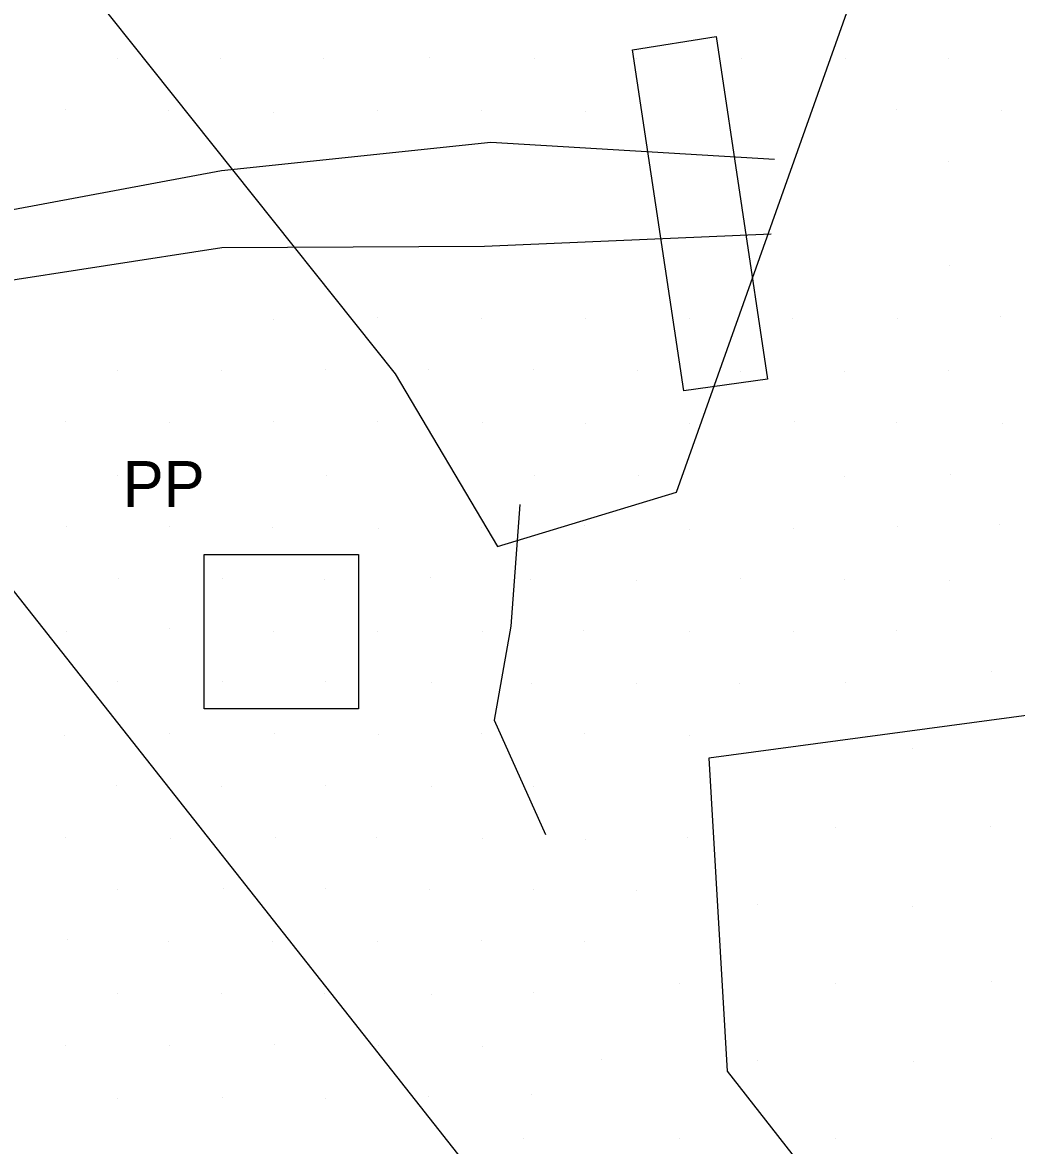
# Model space of a CAD drawing. Extents: x 1602514 to 1609837, y 863887 to 871157.
# Drawn here: x 1605469.8 to 1605605.1, y 866659.7 to 866812.6 of the extents above; entities that cross this region are included whole.
import ezdxf

# ---------------------------------------------------------------- set-up
doc = ezdxf.new("R2010")
doc.units = 0
for name, color, linetype in [('Survey-Flow line', 7, 'Continuous'), ('Survey-Ridge Lines', 7, 'Continuous'), ('Survey-Signs', 7, 'Continuous'), ('Survey-Spot dirt', 7, 'Continuous'), ('Survey-Vegetation trees', 7, 'Continuous'), ('Utility-Pole', 7, 'Continuous')]:
    doc.layers.add(name, color=color, linetype=linetype)

msp = doc.modelspace()

# ---------------------------------------------------------------- linework, layer by layer
at = {"layer": 'Survey-Flow line'}
msp.add_lwpolyline([(1605537.51, 866746.95), (1605536.31, 866730.41), (1605534.05, 866717.59), (1605541.03, 866702.04)], dxfattribs=at)
msp.add_lwpolyline([(1605537.51, 866746.95), (1605536.31, 866730.41), (1605534.05, 866717.59), (1605541.03, 866702.04)], dxfattribs=at)
at = {"layer": 'Survey-Ridge Lines'}
for points in [[(1605271.01, 866733.55), (1605271.13, 866733.84), (1605289.06, 866764.85), (1605290.46, 866799.29), (1605315.08, 866805.27), (1605342.58, 866794.72), (1605372.7, 866790.88), (1605403.41, 866786.28), (1605432.05, 866784.47), (1605463.64, 866786.21), (1605496.91, 866792.44), (1605533.57, 866796.29), (1605572.16, 866793.97)], [(1605271.13, 866733.84), (1605289.06, 866764.85), (1605290.46, 866799.29), (1605315.08, 866805.27), (1605342.58, 866794.72), (1605372.7, 866790.88), (1605403.41, 866786.28), (1605432.05, 866784.47), (1605463.64, 866786.21), (1605496.91, 866792.44), (1605533.57, 866796.29), (1605572.16, 866793.97)], [(1605315.46, 866789.1), (1605342.69, 866785.48), (1605372.69, 866782.64), (1605403.34, 866780.84), (1605431.74, 866777.29), (1605465.29, 866777.04), (1605496.99, 866781.93), (1605532.71, 866782.11), (1605571.74, 866783.81)], [(1605315.46, 866789.1), (1605342.69, 866785.48), (1605372.69, 866782.64), (1605403.34, 866780.84), (1605431.74, 866777.29), (1605465.29, 866777.04), (1605496.99, 866781.93), (1605532.71, 866782.11), (1605571.74, 866783.81)]]:
    msp.add_lwpolyline(points, dxfattribs=at)
at = {"layer": 'Survey-Signs'}
msp.add_lwpolyline([(1605564.25, 866810.68), (1605571.22, 866764.02), (1605559.84, 866762.46), (1605552.88, 866808.83)], close=True, dxfattribs=at)
msp.add_lwpolyline([(1605564.25, 866810.68), (1605571.22, 866764.02), (1605559.84, 866762.46), (1605552.88, 866808.83)], close=True, dxfattribs=at)
at = {"layer": 'Survey-Spot dirt'}
for p, q in [((1605482.8, 866807.68), (1605482.8, 866807.68)), ((1605482.8, 866807.68), (1605482.8, 866807.68)), ((1605496.84, 866807.66), (1605496.84, 866807.66)), ((1605496.84, 866807.66), (1605496.84, 866807.66)), ((1605510.83, 866807.65), (1605510.83, 866807.65)), ((1605510.83, 866807.65), (1605510.83, 866807.65)), ((1605525.29, 866807.83), (1605525.29, 866807.83)), ((1605525.29, 866807.83), (1605525.29, 866807.83)), ((1605539.51, 866807.62), (1605539.51, 866807.62)), ((1605539.51, 866807.62), (1605539.51, 866807.62)), ((1605553.41, 866807.7), (1605553.41, 866807.7)), ((1605553.41, 866807.7), (1605553.41, 866807.7)), ((1605567.74, 866807.66), (1605567.74, 866807.66)), ((1605567.74, 866807.66), (1605567.74, 866807.66)), ((1605581.8, 866807.72), (1605581.8, 866807.72)), ((1605581.8, 866807.72), (1605581.8, 866807.72)), ((1605595.92, 866807.68), (1605595.92, 866807.68)), ((1605595.92, 866807.68), (1605595.92, 866807.68)), ((1605475.72, 866800.69), (1605475.72, 866800.69)), ((1605475.72, 866800.69), (1605475.72, 866800.69)), ((1605489.77, 866800.58), (1605489.77, 866800.58)), ((1605489.77, 866800.58), (1605489.77, 866800.58)), ((1605518.16, 866800.57), (1605518.16, 866800.57)), ((1605518.16, 866800.57), (1605518.16, 866800.57)), ((1605532.26, 866800.62), (1605532.26, 866800.62)), ((1605532.26, 866800.62), (1605532.26, 866800.62)), ((1605546.53, 866800.5), (1605546.53, 866800.5)), ((1605546.53, 866800.5), (1605546.53, 866800.5)), ((1605588.72, 866800.72), (1605588.72, 866800.72)), ((1605588.72, 866800.72), (1605588.72, 866800.72)), ((1605603.04, 866800.62), (1605603.04, 866800.62)), ((1605603.04, 866800.62), (1605603.04, 866800.62)), ((1605504.02, 866800.35), (1605504.02, 866800.35)), ((1605504.02, 866800.35), (1605504.02, 866800.35)), ((1605595.81, 866793.66), (1605595.81, 866793.66)), ((1605595.81, 866793.66), (1605595.81, 866793.66)), ((1605595.99, 866779.44), (1605595.99, 866779.44)), ((1605595.99, 866779.44), (1605595.99, 866779.44)), ((1605504.06, 866772.2), (1605504.06, 866772.2)), ((1605504.06, 866772.2), (1605504.06, 866772.2)), ((1605518.18, 866772.41), (1605518.18, 866772.41)), ((1605518.18, 866772.41), (1605518.18, 866772.41)), ((1605532.32, 866772.28), (1605532.32, 866772.28)), ((1605532.32, 866772.28), (1605532.32, 866772.28)), ((1605546.44, 866772.24), (1605546.44, 866772.24)), ((1605546.44, 866772.24), (1605546.44, 866772.24)), ((1605560.68, 866772.32), (1605560.68, 866772.32)), ((1605560.68, 866772.32), (1605560.68, 866772.32)), ((1605574.59, 866772.26), (1605574.59, 866772.26)), ((1605574.59, 866772.26), (1605574.59, 866772.26)), ((1605588.95, 866772.33), (1605588.95, 866772.33)), ((1605588.95, 866772.33), (1605588.95, 866772.33)), ((1605602.98, 866772.55), (1605602.98, 866772.55)), ((1605602.98, 866772.55), (1605602.98, 866772.55)), ((1605482.83, 866765.27), (1605482.83, 866765.27)), ((1605482.83, 866765.27), (1605482.83, 866765.27)), ((1605511.04, 866765.3), (1605511.04, 866765.3)), ((1605511.04, 866765.3), (1605511.04, 866765.3)), ((1605525.12, 866765.34), (1605525.12, 866765.34)), ((1605525.12, 866765.34), (1605525.12, 866765.34)), ((1605539.32, 866765.3), (1605539.32, 866765.3)), ((1605539.32, 866765.3), (1605539.32, 866765.3)), ((1605496.96, 866765.2), (1605496.96, 866765.2)), ((1605496.96, 866765.2), (1605496.96, 866765.2)), ((1605553.6, 866765.22), (1605553.6, 866765.22)), ((1605553.6, 866765.22), (1605553.6, 866765.22)), ((1605567.6, 866765.08), (1605567.6, 866765.08)), ((1605567.6, 866765.08), (1605567.6, 866765.08)), ((1605581.7, 866765.09), (1605581.7, 866765.09)), ((1605581.7, 866765.09), (1605581.7, 866765.09)), ((1605595.9, 866765.16), (1605595.9, 866765.16)), ((1605595.9, 866765.16), (1605595.9, 866765.16)), ((1605475.7, 866758.31), (1605475.7, 866758.31)), ((1605475.7, 866758.31), (1605475.7, 866758.31)), ((1605489.85, 866758.13), (1605489.85, 866758.13)), ((1605489.85, 866758.13), (1605489.85, 866758.13)), ((1605503.99, 866758.25), (1605503.99, 866758.25)), ((1605503.99, 866758.25), (1605503.99, 866758.25)), ((1605518.11, 866758.24), (1605518.11, 866758.24)), ((1605518.11, 866758.24), (1605518.11, 866758.24)), ((1605532.4, 866758.08), (1605532.4, 866758.08)), ((1605532.4, 866758.08), (1605532.4, 866758.08)), ((1605546.53, 866757.96), (1605546.53, 866757.96)), ((1605546.53, 866757.96), (1605546.53, 866757.96)), ((1605560.56, 866757.94), (1605560.56, 866757.94)), ((1605560.56, 866757.94), (1605560.56, 866757.94)), ((1605574.85, 866758.28), (1605574.85, 866758.28)), ((1605574.85, 866758.28), (1605574.85, 866758.28)), ((1605588.77, 866758.16), (1605588.77, 866758.16)), ((1605588.77, 866758.16), (1605588.77, 866758.16)), ((1605603.17, 866758.05), (1605603.17, 866758.05)), ((1605603.17, 866758.05), (1605603.17, 866758.05)), ((1605482.77, 866750.9), (1605482.77, 866750.9)), ((1605482.77, 866750.9), (1605482.77, 866750.9)), ((1605511.26, 866750.94), (1605511.26, 866750.94)), ((1605511.26, 866750.94), (1605511.26, 866750.94)), ((1605539.56, 866750.85), (1605539.56, 866750.85)), ((1605539.56, 866750.85), (1605539.56, 866750.85)), ((1605553.61, 866750.87), (1605553.61, 866750.87)), ((1605553.61, 866750.87), (1605553.61, 866750.87)), ((1605581.64, 866750.8), (1605581.64, 866750.8)), ((1605581.64, 866750.8), (1605581.64, 866750.8)), ((1605596.18, 866751.01), (1605596.18, 866751.01)), ((1605596.18, 866751.01), (1605596.18, 866751.01)), ((1605475.81, 866744.03), (1605475.81, 866744.03)), ((1605475.81, 866744.03), (1605475.81, 866744.03)), ((1605489.88, 866744), (1605489.88, 866744)), ((1605489.88, 866744), (1605489.88, 866744)), ((1605503.93, 866743.87), (1605503.93, 866743.87)), ((1605503.93, 866743.87), (1605503.93, 866743.87)), ((1605532.29, 866743.87), (1605532.29, 866743.87)), ((1605532.29, 866743.87), (1605532.29, 866743.87)), ((1605546.29, 866744.06), (1605546.29, 866744.06)), ((1605546.29, 866744.06), (1605546.29, 866744.06)), ((1605588.98, 866743.91), (1605588.98, 866743.91)), ((1605588.98, 866743.91), (1605588.98, 866743.91)), ((1605602.86, 866744.18), (1605602.86, 866744.18)), ((1605602.86, 866744.18), (1605602.86, 866744.18)), ((1605518.34, 866743.7), (1605518.34, 866743.7)), ((1605518.34, 866743.7), (1605518.34, 866743.7)), ((1605560.59, 866743.63), (1605560.59, 866743.63)), ((1605560.59, 866743.63), (1605560.59, 866743.63)), ((1605574.71, 866743.76), (1605574.71, 866743.76)), ((1605574.71, 866743.76), (1605574.71, 866743.76)), ((1605482.89, 866736.85), (1605482.89, 866736.85)), ((1605482.89, 866736.85), (1605482.89, 866736.85)), ((1605497.13, 866736.89), (1605497.13, 866736.89)), ((1605497.13, 866736.89), (1605497.13, 866736.89)), ((1605510.99, 866736.75), (1605510.99, 866736.75)), ((1605510.99, 866736.75), (1605510.99, 866736.75)), ((1605525.42, 866737.06), (1605525.42, 866737.06)), ((1605525.42, 866737.06), (1605525.42, 866737.06)), ((1605539.02, 866736.77), (1605539.02, 866736.77)), ((1605539.02, 866736.77), (1605539.02, 866736.77)), ((1605553.45, 866736.62), (1605553.45, 866736.62)), ((1605553.45, 866736.62), (1605553.45, 866736.62)), ((1605567.6, 866736.88), (1605567.6, 866736.88)), ((1605567.6, 866736.88), (1605567.6, 866736.88)), ((1605581.68, 866736.79), (1605581.68, 866736.79)), ((1605581.68, 866736.79), (1605581.68, 866736.79)), ((1605595.96, 866736.68), (1605595.96, 866736.68)), ((1605595.96, 866736.68), (1605595.96, 866736.68)), ((1605475.8, 866729.72), (1605475.8, 866729.72)), ((1605475.8, 866729.72), (1605475.8, 866729.72)), ((1605489.82, 866730.03), (1605489.82, 866730.03)), ((1605489.82, 866730.03), (1605489.82, 866730.03)), ((1605504.04, 866729.65), (1605504.04, 866729.65)), ((1605504.04, 866729.65), (1605504.04, 866729.65)), ((1605518.16, 866729.71), (1605518.16, 866729.71)), ((1605518.16, 866729.71), (1605518.16, 866729.71)), ((1605532.42, 866729.72), (1605532.42, 866729.72)), ((1605532.42, 866729.72), (1605532.42, 866729.72)), ((1605546.23, 866729.88), (1605546.23, 866729.88)), ((1605546.23, 866729.88), (1605546.23, 866729.88)), ((1605560.6, 866729.71), (1605560.6, 866729.71)), ((1605560.6, 866729.71), (1605560.6, 866729.71)), ((1605574.76, 866729.71), (1605574.76, 866729.71)), ((1605574.76, 866729.71), (1605574.76, 866729.71)), ((1605588.84, 866729.86), (1605588.84, 866729.86)), ((1605588.84, 866729.86), (1605588.84, 866729.86)), ((1605601.77, 866724.28), (1605601.77, 866724.28)), ((1605601.77, 866724.28), (1605601.77, 866724.28)), ((1605482.82, 866722.81), (1605482.82, 866722.81)), ((1605482.82, 866722.81), (1605482.82, 866722.81)), ((1605497.04, 866722.91), (1605497.04, 866722.91)), ((1605497.04, 866722.91), (1605497.04, 866722.91)), ((1605511.08, 866722.83), (1605511.08, 866722.83)), ((1605511.08, 866722.83), (1605511.08, 866722.83)), ((1605525.5, 866722.73), (1605525.5, 866722.73)), ((1605525.5, 866722.73), (1605525.5, 866722.73)), ((1605539.17, 866722.58), (1605539.17, 866722.58)), ((1605539.17, 866722.58), (1605539.17, 866722.58)), ((1605553.41, 866722.62), (1605553.41, 866722.62)), ((1605553.41, 866722.62), (1605553.41, 866722.62)), ((1605567.46, 866722.64), (1605567.46, 866722.64)), ((1605567.46, 866722.64), (1605567.46, 866722.64)), ((1605581.78, 866722.77), (1605581.78, 866722.77)), ((1605581.78, 866722.77), (1605581.78, 866722.77)), ((1605475.56, 866715.51), (1605475.56, 866715.51)), ((1605475.56, 866715.51), (1605475.56, 866715.51)), ((1605489.88, 866715.76), (1605489.88, 866715.76)), ((1605489.88, 866715.76), (1605489.88, 866715.76)), ((1605504.18, 866715.77), (1605504.18, 866715.77)), ((1605504.18, 866715.77), (1605504.18, 866715.77)), ((1605518.25, 866715.7), (1605518.25, 866715.7)), ((1605518.25, 866715.7), (1605518.25, 866715.7)), ((1605532.28, 866715.8), (1605532.28, 866715.8)), ((1605532.28, 866715.8), (1605532.28, 866715.8)), ((1605546.34, 866715.81), (1605546.34, 866715.81)), ((1605546.34, 866715.81), (1605546.34, 866715.81)), ((1605560.57, 866715.57), (1605560.57, 866715.57)), ((1605560.57, 866715.57), (1605560.57, 866715.57)), ((1605591.01, 866713.79), (1605591.01, 866713.79)), ((1605591.01, 866713.79), (1605591.01, 866713.79)), ((1605482.69, 866708.72), (1605482.69, 866708.72)), ((1605482.69, 866708.72), (1605482.69, 866708.72)), ((1605511.12, 866708.77), (1605511.12, 866708.77)), ((1605511.12, 866708.77), (1605511.12, 866708.77)), ((1605496.9, 866708.65), (1605496.9, 866708.65)), ((1605496.9, 866708.65), (1605496.9, 866708.65)), ((1605525.47, 866708.64), (1605525.47, 866708.64)), ((1605525.47, 866708.64), (1605525.47, 866708.64)), ((1605539.33, 866708.63), (1605539.33, 866708.63)), ((1605539.33, 866708.63), (1605539.33, 866708.63)), ((1605580.54, 866702.95), (1605580.54, 866702.95)), ((1605580.54, 866702.95), (1605580.54, 866702.95)), ((1605601.51, 866703.16), (1605601.51, 866703.16)), ((1605601.51, 866703.16), (1605601.51, 866703.16)), ((1605475.74, 866701.65), (1605475.74, 866701.65)), ((1605475.74, 866701.65), (1605475.74, 866701.65)), ((1605489.99, 866701.5), (1605489.99, 866701.5)), ((1605489.99, 866701.5), (1605489.99, 866701.5)), ((1605504.22, 866701.61), (1605504.22, 866701.61)), ((1605504.22, 866701.61), (1605504.22, 866701.61)), ((1605518.06, 866701.65), (1605518.06, 866701.65)), ((1605518.06, 866701.65), (1605518.06, 866701.65)), ((1605532.38, 866701.57), (1605532.38, 866701.57)), ((1605532.38, 866701.57), (1605532.38, 866701.57)), ((1605546.4, 866701.41), (1605546.4, 866701.41)), ((1605546.4, 866701.41), (1605546.4, 866701.41)), ((1605560.37, 866701.64), (1605560.37, 866701.64)), ((1605560.37, 866701.64), (1605560.37, 866701.64)), ((1605482.78, 866694.61), (1605482.78, 866694.61)), ((1605482.78, 866694.61), (1605482.78, 866694.61)), ((1605497.16, 866694.74), (1605497.16, 866694.74)), ((1605497.16, 866694.74), (1605497.16, 866694.74)), ((1605511.12, 866694.65), (1605511.12, 866694.65)), ((1605511.12, 866694.65), (1605511.12, 866694.65)), ((1605525.26, 866694.57), (1605525.26, 866694.57)), ((1605525.26, 866694.57), (1605525.26, 866694.57)), ((1605539.4, 866694.52), (1605539.4, 866694.52)), ((1605539.4, 866694.52), (1605539.4, 866694.52)), ((1605553.47, 866694.44), (1605553.47, 866694.44)), ((1605553.47, 866694.44), (1605553.47, 866694.44)), ((1605569.81, 866692.55), (1605569.81, 866692.55)), ((1605569.81, 866692.55), (1605569.81, 866692.55)), ((1605591.01, 866692.3), (1605591.01, 866692.3)), ((1605591.01, 866692.3), (1605591.01, 866692.3)), ((1605475.93, 866687.72), (1605475.93, 866687.72)), ((1605475.93, 866687.72), (1605475.93, 866687.72)), ((1605489.76, 866687.45), (1605489.76, 866687.45)), ((1605489.76, 866687.45), (1605489.76, 866687.45)), ((1605503.9, 866687.5), (1605503.9, 866687.5)), ((1605503.9, 866687.5), (1605503.9, 866687.5)), ((1605518.17, 866687.51), (1605518.17, 866687.51)), ((1605518.17, 866687.51), (1605518.17, 866687.51)), ((1605532.29, 866687.56), (1605532.29, 866687.56)), ((1605532.29, 866687.56), (1605532.29, 866687.56)), ((1605546.35, 866687.49), (1605546.35, 866687.49)), ((1605546.35, 866687.49), (1605546.35, 866687.49)), ((1605559.3, 866681.74), (1605559.3, 866681.74)), ((1605559.3, 866681.74), (1605559.3, 866681.74)), ((1605580.43, 866681.79), (1605580.43, 866681.79)), ((1605580.43, 866681.79), (1605580.43, 866681.79)), ((1605601.72, 866681.98), (1605601.72, 866681.98)), ((1605601.72, 866681.98), (1605601.72, 866681.98)), ((1605482.77, 866680.44), (1605482.77, 866680.44)), ((1605482.77, 866680.44), (1605482.77, 866680.44)), ((1605496.91, 866680.4), (1605496.91, 866680.4)), ((1605496.91, 866680.4), (1605496.91, 866680.4)), ((1605510.96, 866680.42), (1605510.96, 866680.42)), ((1605510.96, 866680.42), (1605510.96, 866680.42)), ((1605525.48, 866680.25), (1605525.48, 866680.25)), ((1605525.48, 866680.25), (1605525.48, 866680.25)), ((1605539.38, 866680.51), (1605539.38, 866680.51)), ((1605539.38, 866680.51), (1605539.38, 866680.51)), ((1605475.69, 866673.39), (1605475.69, 866673.39)), ((1605475.69, 866673.39), (1605475.69, 866673.39)), ((1605489.85, 866673.28), (1605489.85, 866673.28)), ((1605489.85, 866673.28), (1605489.85, 866673.28)), ((1605504.16, 866673.49), (1605504.16, 866673.49)), ((1605504.16, 866673.49), (1605504.16, 866673.49)), ((1605518.24, 866673.29), (1605518.24, 866673.29)), ((1605518.24, 866673.29), (1605518.24, 866673.29)), ((1605532.44, 866673.19), (1605532.44, 866673.19)), ((1605532.44, 866673.19), (1605532.44, 866673.19)), ((1605548.64, 866671.38), (1605548.64, 866671.38)), ((1605548.64, 866671.38), (1605548.64, 866671.38)), ((1605569.88, 866671.31), (1605569.88, 866671.31)), ((1605569.88, 866671.31), (1605569.88, 866671.31)), ((1605591.15, 866671.18), (1605591.15, 866671.18)), ((1605591.15, 866671.18), (1605591.15, 866671.18)), ((1605482.76, 866666.17), (1605482.76, 866666.17)), ((1605482.76, 866666.17), (1605482.76, 866666.17)), ((1605497.03, 866666.21), (1605497.03, 866666.21)), ((1605497.03, 866666.21), (1605497.03, 866666.21)), ((1605511.06, 866666.14), (1605511.06, 866666.14)), ((1605511.06, 866666.14), (1605511.06, 866666.14)), ((1605525.09, 866666.37), (1605525.09, 866666.37)), ((1605525.09, 866666.37), (1605525.09, 866666.37)), ((1605539.15, 866666.66), (1605539.15, 866666.66)), ((1605539.15, 866666.66), (1605539.15, 866666.66)), ((1605538.04, 866660.67), (1605538.04, 866660.67)), ((1605538.04, 866660.67), (1605538.04, 866660.67)), ((1605559.28, 866660.69), (1605559.28, 866660.69)), ((1605559.28, 866660.69), (1605559.28, 866660.69)), ((1605580.53, 866660.64), (1605580.53, 866660.64)), ((1605580.53, 866660.64), (1605580.53, 866660.64)), ((1605601.74, 866660.73), (1605601.74, 866660.73)), ((1605601.74, 866660.73), (1605601.74, 866660.73))]:
    msp.add_line(p, q, dxfattribs=at)
at = {"layer": 'Survey-Vegetation trees'}
msp.add_lwpolyline([(1605470.92, 866827.06), (1605520.55, 866764.77), (1605534.48, 866741.24), (1605558.86, 866748.65), (1605584.98, 866822.27), (1605536.66, 866848.41), (1605482.23, 866851.89)], close=True, dxfattribs=at)
msp.add_lwpolyline([(1605470.92, 866827.06), (1605520.55, 866764.77), (1605534.48, 866741.24), (1605558.86, 866748.65), (1605584.98, 866822.27), (1605536.66, 866848.41), (1605482.23, 866851.89)], close=True, dxfattribs=at)
for points in [[(1605601.79, 866275.83), (1605605.2, 866448.65), (1605612.42, 866530.39), (1605609.93, 866556.1), (1605459.73, 866746.47), (1605424.26, 866753.41), (1605387.87, 866745.45), (1605328.37, 866764.72), (1605298.66, 866722.79), (1605306.28, 866699.16), (1605277.32, 866658.75), (1605265.13, 866625.97), (1605217.79, 866602.88), (1605158.36, 866628.8), (1605148.45, 866592.97), (1605247.5, 866507.58), (1605323.27, 866431.24), (1605384.81, 866367.9), (1605438.61, 866328.19), (1605473.87, 866349.1), (1605499.88, 866323.66)], [(1605601.79, 866275.83), (1605605.2, 866448.65), (1605612.42, 866530.39), (1605609.93, 866556.1), (1605459.73, 866746.47), (1605424.26, 866753.41), (1605387.87, 866745.45), (1605328.37, 866764.72), (1605298.66, 866722.79), (1605306.28, 866699.16), (1605277.32, 866658.75), (1605265.13, 866625.97), (1605217.79, 866602.88), (1605158.36, 866628.8), (1605148.45, 866592.97), (1605247.5, 866507.58), (1605323.27, 866431.24), (1605384.81, 866367.9), (1605438.61, 866328.19), (1605473.87, 866349.1), (1605499.88, 866323.66)], [(1605933.61, 866558.21), (1605731.71, 866735.08), (1605563.24, 866712.42), (1605565.76, 866669.83), (1605667.1, 866540.23), (1605670.14, 866448.74), (1605652.62, 866371.74), (1605654.91, 866272.63), (1605846.15, 866251.29), (1605868.24, 866270.35), (1605917, 866264.25)], [(1605933.61, 866558.21), (1605731.71, 866735.08), (1605563.24, 866712.42), (1605565.76, 866669.83), (1605667.1, 866540.23), (1605670.14, 866448.74), (1605652.62, 866371.74), (1605654.91, 866272.63), (1605846.15, 866251.29), (1605868.24, 866270.35), (1605917, 866264.25)]]:
    msp.add_lwpolyline(points, dxfattribs=at)
at = {"layer": 'Utility-Pole'}
msp.add_lwpolyline([(1605494.55, 866740.16), (1605515.56, 866740.16), (1605515.56, 866719.15), (1605494.55, 866719.15)], close=True, dxfattribs=at)
msp.add_lwpolyline([(1605494.55, 866740.16), (1605515.56, 866740.16), (1605515.56, 866719.15), (1605494.55, 866719.15)], close=True, dxfattribs=at)

# ---------------------------------------------------------------- texts
msp.add_text('PP', height=6.251, dxfattribs=at).set_placement((1605483.49, 866746.63))
msp.add_text('PP', height=6.251, dxfattribs=at).set_placement((1605483.49, 866746.63))

doc.saveas('drawing.dxf')
